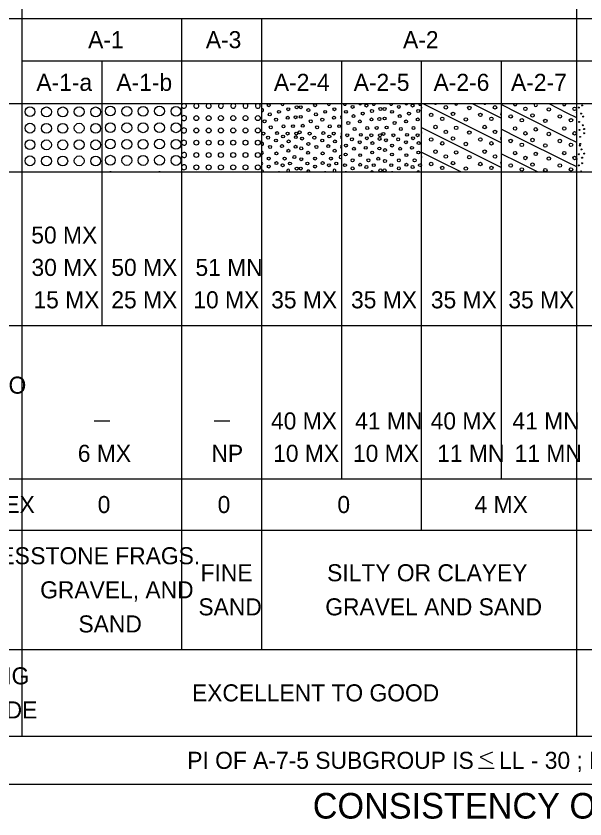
# Model space of a CAD drawing. Extents: x 265553 to 275568, y 168312 to 173522.
# Drawn here: x 266960.1 to 267104.8, y 170744.9 to 170949.1 of the extents above; entities that cross this region are included whole.
import ezdxf

# ---------------------------------------------------------------- set-up
doc = ezdxf.new("R2010")
doc.units = 0
doc.layers.add('Geotech Sheets and Borders Cell', color=7, linetype='Continuous')

msp = doc.modelspace()

# ---------------------------------------------------------------- linework, layer by layer
at = {"layer": 'Geotech Sheets and Borders Cell'}
for p, q in [((266961.63, 170970.22), (266961.63, 170765.99)), ((267102.61, 170970.22), (267102.61, 170765.99)), ((266920.42, 170948.53), (267297.82, 170948.53)), ((267002.32, 170788.03), (267002.32, 170948.53)), ((267022.62, 170788.03), (267022.62, 170948.53)), ((266961.63, 170937.69), (267185.03, 170937.69)), ((266982.02, 170870.45), (266982.02, 170937.69)), ((267042.92, 170831.41), (267042.92, 170937.69)), ((267063.22, 170818.4), (267063.22, 170937.69)), ((267083.53, 170831.41), (267083.53, 170937.69)), ((266920.42, 170926.84), (267297.82, 170926.84)), ((266974.08, 170926.83), (266974.08, 170926.83)), ((266974.08, 170926.83), (266974.09, 170926.82)), ((267063.6, 170926.84), (267067.48, 170924.9)), ((267076.1, 170926.84), (267079.98, 170924.9)), ((267095.58, 170926.84), (267100.2, 170924.52)), ((267067.48, 170924.9), (267079.98, 170918.65)), ((267079.98, 170924.9), (267083.53, 170923.12)), ((267083.53, 170926.61), (267087.7, 170924.52)), ((267087.7, 170924.52), (267100.2, 170918.27)), ((267100.2, 170924.52), (267102.61, 170923.32)), ((267063.22, 170920.77), (267067.48, 170918.65)), ((267083.53, 170920.36), (267087.7, 170918.27)), ((267067.48, 170918.65), (267079.98, 170912.4)), ((267079.98, 170918.65), (267083.53, 170916.87)), ((267087.7, 170918.27), (267100.2, 170912.02)), ((267100.2, 170918.27), (267102.61, 170917.07)), ((266982.02, 170914.47), (266982.02, 170914.46)), ((267063.22, 170914.52), (267067.48, 170912.4)), ((267083.53, 170914.11), (267087.7, 170912.02)), ((267067.48, 170912.4), (267073.3, 170909.49)), ((267079.98, 170912.4), (267083.53, 170910.62)), ((267087.7, 170912.02), (267092.78, 170909.49)), ((267100.2, 170912.02), (267102.61, 170910.82)), ((266920.42, 170909.49), (267297.82, 170909.49)), ((266920.42, 170870.45), (267297.82, 170870.45)), ((266979.98, 170846.16), (266983.97, 170846.16)), ((267010.47, 170846.16), (267014.47, 170846.16)), ((266920.42, 170831.41), (267185.03, 170831.41)), ((266920.42, 170818.4), (267185.03, 170818.4)), ((266920.42, 170788.03), (267297.82, 170788.03)), ((266920.42, 170765.99), (267297.82, 170765.99)), ((267077.72, 170757.82), (267081.71, 170757.82)), ((267670.42, 170753.71), (266920.42, 170753.71))]:
    msp.add_line(p, q, dxfattribs=at)
msp.add_lwpolyline([(267081.3, 170761.93), (267078.14, 170760.63), (267081.3, 170759.07)], dxfattribs=at)
for centre, radius in [((266963.67, 170924.8), 1.25), ((266967.86, 170924.74), 1.25), ((266972, 170924.74), 1.25), ((266976.17, 170924.8), 1.25), ((266980.36, 170924.74), 1.25), ((266984.1, 170924.95), 1.25), ((266988.29, 170924.89), 1.25), ((266992.43, 170924.89), 1.25), ((266996.6, 170924.95), 1.25), ((267000.79, 170924.89), 1.25), ((267024.39, 170926.44), 0.375), ((267026.98, 170924.76), 0.375), ((267029.33, 170925.42), 0.375), ((267031.48, 170925.93), 0.375), ((267032.52, 170925.93), 0.375), ((267034.45, 170925.19), 0.375), ((267036.15, 170926.44), 0.375), ((267038.73, 170924.76), 0.375), ((267041.08, 170925.42), 0.375), ((267043.99, 170924.76), 0.375), ((267045.69, 170926.01), 0.375), ((267049.21, 170926.34), 0.375), ((267050.63, 170924.98), 0.375), ((267052.78, 170925.49), 0.375), ((267053.82, 170925.49), 0.375), ((267055.75, 170924.76), 0.375), ((267057.45, 170926.01), 0.375), ((267060.96, 170926.34), 0.375), ((267062.38, 170924.98), 0.375), ((267069.41, 170925.9), 0.437), ((267075.37, 170925.74), 0.437), ((267081.91, 170925.9), 0.437), ((267089.64, 170925.53), 0.437), ((267095.6, 170925.37), 0.437), ((267102.14, 170925.53), 0.437), ((267103.19, 170925.83), 0.125), ((267104.05, 170926.4), 0.125), ((267005.97, 170923.16), 0.625), ((267009.1, 170923.16), 0.625), ((267012.22, 170923.16), 0.625), ((267015.35, 170923.16), 0.625), ((267018.47, 170923.16), 0.625), ((267021.6, 170923.16), 0.625), ((267024.63, 170924.12), 0.375), ((267026.24, 170922.77), 0.375), ((267029.22, 170923.26), 0.375), ((267031.2, 170923.38), 0.375), ((267032.52, 170923.49), 0.375), ((267036.38, 170924.12), 0.375), ((267038, 170922.77), 0.375), ((267040.97, 170923.26), 0.375), ((267045.93, 170923.68), 0.375), ((267048.28, 170924.32), 0.375), ((267050.51, 170922.82), 0.375), ((267052.5, 170922.94), 0.375), ((267053.82, 170923.06), 0.375), ((267057.68, 170923.68), 0.375), ((267060.03, 170924.32), 0.375), ((267062.27, 170922.82), 0.375), ((267065.68, 170923.98), 0.437), ((267068.5, 170922.99), 0.437), ((267071.22, 170924.23), 0.437), ((267074.48, 170922.83), 0.437), ((267078.18, 170923.98), 0.437), ((267081, 170922.99), 0.437), ((267085.9, 170923.6), 0.437), ((267088.73, 170922.62), 0.437), ((267091.45, 170923.85), 0.437), ((267094.7, 170922.45), 0.437), ((267098.4, 170923.6), 0.437), ((267101.23, 170922.62), 0.437), ((267103.81, 170924.3), 0.125), ((267104.33, 170923.56), 0.125), ((266963.67, 170920.6), 1.25), ((266967.86, 170920.55), 1.25), ((266972, 170920.55), 1.25), ((266976.17, 170920.6), 1.25), ((266980.36, 170920.55), 1.25), ((266984.1, 170920.75), 1.25), ((266988.29, 170920.7), 1.25), ((266992.43, 170920.7), 1.25), ((266996.6, 170920.75), 1.25), ((267000.79, 170920.7), 1.25), ((267023.32, 170922.35), 0.375), ((267024.9, 170920.82), 0.375), ((267028.13, 170921.07), 0.375), ((267030.52, 170921.11), 0.375), ((267033.03, 170921.22), 0.375), ((267035.07, 170922.35), 0.375), ((267036.66, 170920.82), 0.375), ((267039.89, 170921.07), 0.375), ((267042.28, 170921.11), 0.375), ((267044.61, 170921.92), 0.375), ((267046.2, 170920.39), 0.375), ((267047.54, 170922.33), 0.375), ((267049.43, 170920.64), 0.375), ((267051.82, 170920.67), 0.375), ((267054.33, 170920.78), 0.375), ((267056.37, 170921.92), 0.375), ((267057.96, 170920.39), 0.375), ((267059.3, 170922.33), 0.375), ((267061.19, 170920.64), 0.375), ((267066.79, 170920.89), 0.437), ((267072.04, 170920.68), 0.437), ((267079.29, 170920.89), 0.437), ((267087.02, 170920.52), 0.437), ((267092.27, 170920.3), 0.437), ((267099.52, 170920.52), 0.437), ((267103.3, 170922.2), 0.125), ((267104.21, 170921.35), 0.125), ((267005.97, 170920.03), 0.625), ((267009.1, 170920.03), 0.625), ((267012.22, 170920.03), 0.625), ((267015.35, 170920.03), 0.625), ((267018.47, 170920.03), 0.625), ((267021.6, 170920.03), 0.625), ((267023.03, 170919.23), 0.375), ((267026.49, 170919.35), 0.375), ((267028.02, 170918.48), 0.375), ((267029.16, 170919.23), 0.375), ((267031.26, 170918.32), 0.375), ((267031.37, 170919.23), 0.375), ((267032.23, 170919.58), 0.375), ((267034.78, 170919.23), 0.375), ((267038.25, 170919.35), 0.375), ((267039.78, 170918.48), 0.375), ((267040.92, 170919.23), 0.375), ((267044.33, 170918.8), 0.375), ((267047.79, 170918.91), 0.375), ((267050.46, 170918.8), 0.375), ((267052.67, 170918.8), 0.375), ((267053.53, 170919.14), 0.375), ((267056.08, 170918.8), 0.375), ((267059.55, 170918.91), 0.375), ((267062.21, 170918.8), 0.375), ((267069.41, 170919.65), 0.437), ((267075.37, 170919.49), 0.437), ((267081.91, 170919.65), 0.437), ((267089.64, 170919.28), 0.437), ((267095.6, 170919.12), 0.437), ((267102.14, 170919.28), 0.437), ((267103.41, 170920.16), 0.125), ((267104.55, 170920.39), 0.125), ((267104.55, 170919.31), 0.125), ((266963.67, 170916.42), 1.25), ((266967.86, 170916.37), 1.25), ((266972, 170916.37), 1.25), ((266976.17, 170916.42), 1.25), ((266980.36, 170916.37), 1.25), ((266984.1, 170916.56), 1.25), ((266988.29, 170916.51), 1.25), ((266992.43, 170916.51), 1.25), ((266996.6, 170916.56), 1.25), ((267000.79, 170916.51), 1.25), ((267005.97, 170916.91), 0.625), ((267009.1, 170916.91), 0.625), ((267012.22, 170916.91), 0.625), ((267015.35, 170916.91), 0.625), ((267018.47, 170916.91), 0.625), ((267021.6, 170916.91), 0.625), ((267024.22, 170918.2), 0.375), ((267026.21, 170917.47), 0.375), ((267029.44, 170917.23), 0.375), ((267032.86, 170917.97), 0.375), ((267034.45, 170916.6), 0.375), ((267035.98, 170918.2), 0.375), ((267037.97, 170917.47), 0.375), ((267041.2, 170917.23), 0.375), ((267045.52, 170917.77), 0.375), ((267047.51, 170917.03), 0.375), ((267049.32, 170918.05), 0.375), ((267050.74, 170916.8), 0.375), ((267052.56, 170917.88), 0.375), ((267054.16, 170917.53), 0.375), ((267057.28, 170917.77), 0.375), ((267059.26, 170917.03), 0.375), ((267061.08, 170918.05), 0.375), ((267062.5, 170916.8), 0.375), ((267065.68, 170917.73), 0.437), ((267068.5, 170916.74), 0.437), ((267071.22, 170917.98), 0.437), ((267074.48, 170916.58), 0.437), ((267078.18, 170917.73), 0.437), ((267081, 170916.74), 0.437), ((267085.9, 170917.35), 0.437), ((267088.73, 170916.37), 0.437), ((267091.45, 170917.6), 0.437), ((267094.7, 170916.2), 0.437), ((267098.4, 170917.35), 0.437), ((267101.23, 170916.37), 0.437), ((267103.53, 170918.4), 0.125), ((267103.59, 170916.58), 0.125), ((267024.73, 170915.82), 0.375), ((267027.74, 170916.05), 0.375), ((267029.38, 170914.85), 0.375), ((267031.2, 170915.88), 0.375), ((267032.63, 170915.47), 0.375), ((267034.39, 170914.34), 0.375), ((267036.49, 170915.82), 0.375), ((267039.5, 170916.05), 0.375), ((267041.14, 170914.85), 0.375), ((267043.99, 170916.17), 0.375), ((267046.03, 170915.38), 0.375), ((267049.04, 170915.61), 0.375), ((267050.68, 170914.42), 0.375), ((267052.5, 170915.44), 0.375), ((267053.93, 170915.04), 0.375), ((267055.75, 170916.17), 0.375), ((267057.79, 170915.38), 0.375), ((267060.8, 170915.61), 0.375), ((267062.44, 170914.42), 0.375), ((267066.79, 170914.64), 0.437), ((267072.04, 170914.43), 0.437), ((267079.29, 170914.64), 0.437), ((267087.02, 170914.27), 0.437), ((267099.52, 170914.27), 0.437), ((267103.47, 170916.17), 0.125), ((267103.87, 170915.21), 0.125), ((266963.67, 170912.3), 1.25), ((266967.86, 170912.24), 1.25), ((266972, 170912.24), 1.25), ((266976.17, 170912.3), 1.25), ((266980.36, 170912.24), 1.25), ((266984.1, 170912.45), 1.25), ((266988.29, 170912.39), 1.25), ((266992.43, 170912.39), 1.25), ((266996.6, 170912.45), 1.25), ((267000.79, 170912.39), 1.25), ((267005.97, 170913.78), 0.625), ((267009.1, 170913.78), 0.625), ((267012.22, 170913.78), 0.625), ((267015.35, 170913.78), 0.625), ((267018.47, 170913.78), 0.625), ((267021.6, 170913.78), 0.625), ((267024.39, 170912.87), 0.375), ((267026.32, 170914.17), 0.375), ((267028.42, 170912.87), 0.375), ((267030.92, 170913.27), 0.375), ((267032.63, 170912.7), 0.375), ((267036.15, 170912.87), 0.375), ((267038.08, 170914.17), 0.375), ((267040.18, 170912.87), 0.375), ((267043.93, 170913.91), 0.375), ((267045.69, 170912.43), 0.375), ((267047.62, 170913.74), 0.375), ((267049.72, 170912.43), 0.375), ((267052.21, 170912.83), 0.375), ((267053.93, 170912.26), 0.375), ((267055.69, 170913.91), 0.375), ((267057.45, 170912.43), 0.375), ((267059.38, 170913.74), 0.375), ((267061.48, 170912.43), 0.375), ((267069.41, 170913.4), 0.437), ((267075.37, 170913.24), 0.437), ((267081.91, 170913.4), 0.437), ((267089.64, 170913.03), 0.437), ((267092.27, 170914.05), 0.437), ((267095.6, 170912.87), 0.437), ((267102.14, 170913.03), 0.437), ((267103.25, 170913.96), 0.125), ((267104.04, 170913.1), 0.125), ((267104.61, 170914.13), 0.125), ((267005.97, 170910.66), 0.625), ((267009.1, 170910.66), 0.625), ((267012.22, 170910.66), 0.625), ((267015.35, 170910.66), 0.625), ((267018.47, 170910.66), 0.625), ((267021.6, 170910.66), 0.625), ((267024.39, 170910.83), 0.375), ((267026.32, 170911.73), 0.375), ((267027.91, 170911.17), 0.375), ((267029.78, 170911.62), 0.375), ((267031.48, 170910.32), 0.375), ((267032.52, 170910.32), 0.375), ((267034.22, 170911.62), 0.375), ((267036.15, 170910.83), 0.375), ((267038.08, 170911.73), 0.375), ((267039.67, 170911.17), 0.375), ((267041.54, 170911.62), 0.375), ((267043.76, 170911.19), 0.375), ((267045.69, 170910.39), 0.375), ((267047.62, 170911.3), 0.375), ((267049.21, 170910.73), 0.375), ((267051.08, 170911.19), 0.375), ((267055.52, 170911.19), 0.375), ((267057.45, 170910.39), 0.375), ((267059.38, 170911.3), 0.375), ((267060.96, 170910.73), 0.375), ((267062.84, 170911.19), 0.375), ((267065.68, 170911.48), 0.437), ((267068.5, 170910.49), 0.437), ((267071.22, 170911.73), 0.437), ((267074.48, 170910.33), 0.437), ((267078.18, 170911.48), 0.437), ((267081, 170910.49), 0.437), ((267085.9, 170911.1), 0.437), ((267088.73, 170910.12), 0.437), ((267091.45, 170911.35), 0.437), ((267098.4, 170911.1), 0.437), ((267101.23, 170910.12), 0.437), ((267103.19, 170911.12), 0.125), ((267104.05, 170911.69), 0.125), ((267052.78, 170909.88), 0.375), ((267053.82, 170909.88), 0.375), ((267094.7, 170909.95), 0.437)]:
    msp.add_circle(centre, radius, dxfattribs=at)
for centre, radius, start, end in [((267002.85, 170926.28), 0.625, 117.2937, 147.8104), ((267002.85, 170926.28), 0.625, 212.1896, 62.7063), ((267005.97, 170926.28), 0.625, 117.2937, 62.7063), ((267009.1, 170926.28), 0.625, 117.2937, 62.7063), ((267012.22, 170926.28), 0.625, 117.2937, 62.7063), ((267015.35, 170926.28), 0.625, 117.2937, 62.7063), ((267018.47, 170926.28), 0.625, 117.2937, 62.7063), ((267021.6, 170926.28), 0.625, 117.2937, 62.7063), ((267027.91, 170926.78), 0.375, 171.147, 8.853), ((267039.67, 170926.78), 0.375, 171.147, 8.853), ((267043.76, 170926.8), 0.375, 174.4692, 5.5308), ((267047.62, 170926.91), 0.375, 191.7487, 348.2513), ((267051.08, 170926.8), 0.375, 174.4692, 5.5308), ((267055.52, 170926.8), 0.375, 174.4692, 5.5308), ((267059.38, 170926.91), 0.375, 191.7487, 348.2513), ((267062.84, 170926.8), 0.375, 174.4692, 5.5308), ((267066.79, 170927.14), 0.437, 223.6373, 316.3627), ((267072.04, 170926.93), 0.437, 191.793, 348.207), ((267079.29, 170927.14), 0.437, 223.6373, 316.3627), ((267087.02, 170926.77), 0.437, 170.7511, 9.2489), ((267092.27, 170926.55), 0.437, 139.7264, 40.2736), ((267099.52, 170926.77), 0.437, 170.7511, 9.2489), ((267022.69, 170925.19), 0.375, 259.1391, 100.8609), ((267043.24, 170925.93), 0.375, 148.7579, 211.2421), ((267062.87, 170925.74), 0.437, 322.3805, 37.6195), ((267083.1, 170925.37), 0.437, 350.9144, 9.0856), ((267002.85, 170923.16), 0.625, 212.1896, 147.8104), ((267042.96, 170923.38), 0.375, 96.0262, 263.9738), ((267083.72, 170924.23), 0.437, 116.2386, 243.7614), ((267102.51, 170924.64), 0.125, 324.1084, 35.8916), ((267102.56, 170923.23), 0.125, 291.108, 68.892), ((267042.57, 170920.78), 0.375, 338.4467, 21.5533), ((267063.58, 170920.67), 0.375, 162.3921, 197.6079), ((267002.85, 170920.03), 0.625, 212.1896, 147.8104), ((267043.02, 170918.32), 0.375, 104.7726, 255.2274), ((267043.13, 170919.23), 0.375, 123.7096, 236.2904), ((267062.87, 170919.49), 0.437, 322.3805, 37.6195), ((267083.1, 170919.12), 0.437, 350.9144, 9.0856), ((267002.85, 170916.91), 0.625, 212.1896, 147.8104), ((267022.69, 170916.6), 0.375, 259.1391, 100.8609), ((267083.72, 170917.98), 0.437, 116.2386, 243.7614), ((267102.56, 170917.55), 0.125, 291.108, 68.892), ((267022.63, 170914.34), 0.375, 267.7979, 92.2021), ((267042.96, 170915.88), 0.375, 96.0262, 263.9738), ((267002.85, 170913.78), 0.625, 212.1896, 147.8104), ((267042.67, 170913.27), 0.375, 48.5716, 311.4284), ((267062.87, 170913.24), 0.437, 322.3805, 37.6195), ((267083.1, 170912.87), 0.437, 350.9144, 9.0856), ((267102.68, 170912.76), 0.125, 237.325, 122.675), ((267002.85, 170910.66), 0.625, 212.1896, 147.8104), ((267022.47, 170911.62), 0.375, 294.3038, 65.6962), ((267043.24, 170910.32), 0.375, 148.7579, 211.2421), ((267083.72, 170911.73), 0.437, 116.2386, 243.7614), ((266984.1, 170908.25), 1.25, 82.1331, 97.8669), ((266996.6, 170908.25), 1.25, 82.1331, 97.8669), ((267022.69, 170909.58), 0.375, 345.7476, 100.8609), ((267026.98, 170909.15), 0.375, 64.663, 115.337), ((267029.33, 170909.8), 0.375, 302.2, 237.8), ((267034.45, 170909.58), 0.375, 345.7476, 194.2524), ((267038.73, 170909.15), 0.375, 64.663, 115.337), ((267041.08, 170909.8), 0.375, 302.2, 237.8), ((267043.99, 170909.14), 0.375, 65.917, 114.083), ((267050.63, 170909.37), 0.375, 18.2374, 161.7626), ((267055.75, 170909.14), 0.375, 65.917, 114.083), ((267062.38, 170909.37), 0.375, 18.2374, 161.7626), ((267102.51, 170909.93), 0.125, 324.1084, 35.8916), ((267103.81, 170909.59), 0.125, 305.1764, 234.8236)]:
    msp.add_arc(centre, radius, start, end, dxfattribs=at)

# ---------------------------------------------------------------- texts
for s, height, p in [('A-1', 4.338, (266978.45, 170940.94)), ('A-3', 4.338, (267008.38, 170940.94)), ('A-2', 4.338, (267058.53, 170940.94)), ('A-1-a', 4.338, (266965.29, 170930.09)), ('A-1-b', 4.338, (266985.63, 170930.09)), ('A-2-4', 4.338, (267025.68, 170930.09)), ('A-2-5', 4.338, (267045.98, 170930.09)), ('A-2-6', 4.338, (267066.29, 170930.09)), ('A-2-7', 4.338, (267085.98, 170930.09)), ('50 MX', 4.338, (266964, 170891.26)), ('30 MX', 4.338, (266964.05, 170883.03)), ('50 MX', 4.338, (266984.35, 170883.03)), ('51 MN', 4.338, (267005.75, 170883.03)), ('15 MX', 4.338, (266964.55, 170874.79)), ('25 MX', 4.338, (266984.35, 170874.79)), ('10 MX', 4.338, (267005.2, 170874.79)), ('35 MX', 4.338, (267025, 170874.79)), ('35 MX', 4.338, (267045.3, 170874.79)), ('35 MX', 4.338, (267065.6, 170874.79)), ('35 MX', 4.338, (267085.3, 170874.79)), ('PASSING #4O', 4.3381, (266924.36, 170853.09)), ('40 MX', 4.338, (267024.95, 170843.99)), ('41 MN', 4.338, (267046.35, 170843.99)), ('40 MX', 4.338, (267065.55, 170843.99)), ('41 MN', 4.338, (267086.35, 170843.99)), ('6 MX', 4.338, (266975.83, 170835.75)), ('NP', 4.338, (267009.81, 170835.75)), ('10 MX', 4.338, (267025.5, 170835.75)), ('10 MX', 4.338, (267045.8, 170835.75)), ('11 MN', 4.338, (267067.21, 170835.75)), ('11 MN', 4.338, (267086.9, 170835.75)), ('GROUP INDEX', 4.3381, (266924.28, 170822.73)), ('0', 4.34, (266980.88, 170822.73)), ('0', 4.34, (267011.38, 170822.73)), ('0', 4.34, (267041.83, 170822.73)), ('4 MX', 4.338, (267076.72, 170822.73)), ('USUAL TYPES', 4.3381, (266923.65, 170809.71)), ('STONE FRAGS.', 4.3381, (266963.75, 170809.71)), ('FINE', 4.338, (267007.04, 170805.38)), ('SILTY OR CLAYEY', 4.3381, (267039.22, 170805.38)), ('GRAVEL, AND', 4.3381, (266966.26, 170801.04)), ('SAND', 4.338, (267006.49, 170796.71)), ('GRAVEL AND SAND', 4.3381, (267038.75, 170796.71)), ('SAND', 4.338, (266975.99, 170792.37)), ('GEN. RATING', 4.3381, (266925.78, 170779.17)), ('EXCELLENT TO GOOD', 4.3381, (267004.86, 170774.84)), ('AS SUBGRADE', 4.3381, (266923.63, 170770.5)), ('PI OF A-7-5 SUBGROUP IS    LL - 30 ; PI OF A-7-6 SUBGROUP IS   LL - 30', 4.3381, (267003.66, 170757.68)), ('CONSISTENCY OR DENSENESS', 6.507, (267035.57, 170745.04))]:
    msp.add_text(s, height=height, dxfattribs=at).set_placement(p)

doc.saveas('drawing.dxf')
